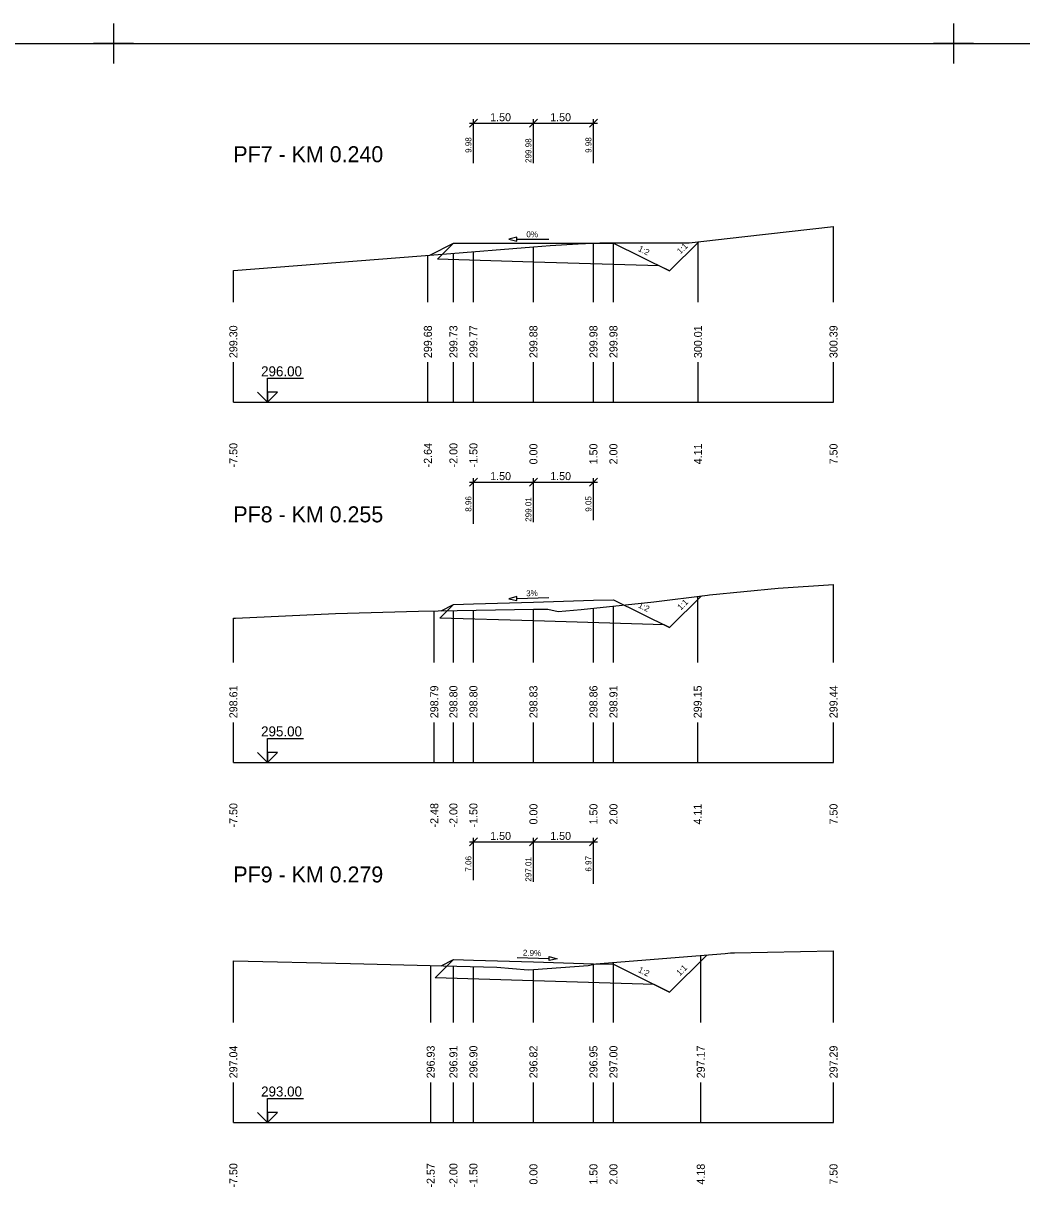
# Model space of a CAD drawing. Extents: x -5 to 1265, y -2 to 602.
# Drawn here: x 397.5 to 647, y 307.8 to 601.7 of the extents above; entities that cross this region are included whole.
import ezdxf

# ---------------------------------------------------------------- set-up
doc = ezdxf.new("R2010")
doc.units = 0
for name, color, linetype in [('KOTA', 7, 'Continuous'), ('KOTA_DELKY', 7, 'Continuous'), ('KOTA_DELKY_CONT', 7, 'Continuous'), ('NS_TELESO_VOZOVKY', 7, 'Continuous'), ('NS_V_PF', 7, 'Continuous'), ('REZY_PF_PUVODNI', 7, 'Continuous'), ('SESTAVY_REZU_PF', 7, 'Continuous'), ('SKLON', 7, 'Continuous'), ('SVK', 7, 'Continuous')]:
    doc.layers.add(name, color=color, linetype=linetype)

msp = doc.modelspace()

# ---------------------------------------------------------------- linework, layer by layer
for p, q in [((420, 601.67), (420, 591.67)), ((420, 601.67), (420, 591.67)), ((420, 601.67), (420, 591.67)), ((420, 601.67), (420, 591.67)), ((420, 601.67), (420, 591.67)), ((420, 601.67), (420, 591.67)), ((420, 601.67), (420, 591.67)), ((420, 601.67), (420, 591.67)), ((420, 601.67), (420, 591.67)), ((420, 601.67), (420, 591.67)), ((420, 601.67), (420, 591.67)), ((420, 601.67), (420, 591.67)), ((420, 601.67), (420, 591.67)), ((420, 601.67), (420, 591.67)), ((420, 601.67), (420, 591.67)), ((420, 601.67), (420, 591.67)), ((420, 601.67), (420, 591.67)), ((420, 601.67), (420, 591.67)), ((420, 601.67), (420, 591.67)), ((420, 601.67), (420, 591.67)), ((420, 601.67), (420, 591.67)), ((420, 601.67), (420, 591.67)), ((420, 601.67), (420, 591.67)), ((420, 601.67), (420, 591.67)), ((420, 601.67), (420, 591.67)), ((420, 601.67), (420, 591.67)), ((420, 601.67), (420, 591.67)), ((420, 601.67), (420, 591.67)), ((420, 601.67), (420, 591.67)), ((420, 601.67), (420, 591.67)), ((420, 601.67), (420, 591.67)), ((420, 601.67), (420, 591.67)), ((420, 601.67), (420, 591.67)), ((420, 601.67), (420, 591.67)), ((420, 601.67), (420, 591.67)), ((420, 601.67), (420, 591.67)), ((420, 601.67), (420, 591.67)), ((420, 601.67), (420, 591.67)), ((420, 601.67), (420, 591.67)), ((420, 601.67), (420, 591.67)), ((420, 601.67), (420, 591.67)), ((420, 601.67), (420, 591.67)), ((420, 601.67), (420, 591.67)), ((420, 601.67), (420, 591.67)), ((420, 601.67), (420, 591.67)), ((420, 601.67), (420, 591.67)), ((420, 601.67), (420, 591.67)), ((420, 601.67), (420, 591.67)), ((420, 601.67), (420, 591.67)), ((420, 601.67), (420, 591.67)), ((420, 601.67), (420, 591.67)), ((420, 601.67), (420, 591.67)), ((420, 601.67), (420, 591.67)), ((420, 601.67), (420, 591.67)), ((630, 601.67), (630, 591.67)), ((630, 601.67), (630, 591.67)), ((630, 601.67), (630, 591.67)), ((630, 601.67), (630, 591.67)), ((630, 601.67), (630, 591.67)), ((630, 601.67), (630, 591.67)), ((630, 601.67), (630, 591.67)), ((630, 601.67), (630, 591.67)), ((630, 601.67), (630, 591.67)), ((630, 601.67), (630, 591.67)), ((630, 601.67), (630, 591.67)), ((630, 601.67), (630, 591.67)), ((630, 601.67), (630, 591.67)), ((630, 601.67), (630, 591.67)), ((630, 601.67), (630, 591.67)), ((630, 601.67), (630, 591.67)), ((630, 601.67), (630, 591.67)), ((630, 601.67), (630, 591.67)), ((630, 601.67), (630, 591.67)), ((630, 601.67), (630, 591.67)), ((630, 601.67), (630, 591.67)), ((630, 601.67), (630, 591.67)), ((630, 601.67), (630, 591.67)), ((630, 601.67), (630, 591.67)), ((630, 601.67), (630, 591.67)), ((630, 601.67), (630, 591.67)), ((630, 601.67), (630, 591.67)), ((630, 601.67), (630, 591.67)), ((630, 601.67), (630, 591.67)), ((630, 601.67), (630, 591.67)), ((630, 601.67), (630, 591.67)), ((630, 601.67), (630, 591.67)), ((630, 601.67), (630, 591.67)), ((630, 601.67), (630, 591.67)), ((630, 601.67), (630, 591.67)), ((630, 601.67), (630, 591.67)), ((630, 601.67), (630, 591.67)), ((630, 601.67), (630, 591.67)), ((630, 601.67), (630, 591.67)), ((630, 601.67), (630, 591.67)), ((630, 601.67), (630, 591.67)), ((630, 601.67), (630, 591.67)), ((630, 601.67), (630, 591.67)), ((630, 601.67), (630, 591.67)), ((630, 601.67), (630, 591.67)), ((630, 601.67), (630, 591.67)), ((630, 601.67), (630, 591.67)), ((630, 601.67), (630, 591.67)), ((630, 601.67), (630, 591.67)), ((630, 601.67), (630, 591.67)), ((630, 601.67), (630, 591.67)), ((630, 601.67), (630, 591.67)), ((630, 601.67), (630, 591.67)), ((630, 601.67), (630, 591.67)), ((425, 596.67), (415, 596.67)), ((425, 596.67), (415, 596.67)), ((425, 596.67), (415, 596.67)), ((425, 596.67), (415, 596.67)), ((425, 596.67), (415, 596.67)), ((425, 596.67), (415, 596.67)), ((425, 596.67), (415, 596.67)), ((425, 596.67), (415, 596.67)), ((425, 596.67), (415, 596.67)), ((425, 596.67), (415, 596.67)), ((425, 596.67), (415, 596.67)), ((425, 596.67), (415, 596.67)), ((425, 596.67), (415, 596.67)), ((425, 596.67), (415, 596.67)), ((425, 596.67), (415, 596.67)), ((425, 596.67), (415, 596.67)), ((425, 596.67), (415, 596.67)), ((425, 596.67), (415, 596.67)), ((425, 596.67), (415, 596.67)), ((425, 596.67), (415, 596.67)), ((425, 596.67), (415, 596.67)), ((425, 596.67), (415, 596.67)), ((425, 596.67), (415, 596.67)), ((425, 596.67), (415, 596.67)), ((425, 596.67), (415, 596.67)), ((425, 596.67), (415, 596.67)), ((425, 596.67), (415, 596.67)), ((425, 596.67), (415, 596.67)), ((425, 596.67), (415, 596.67)), ((425, 596.67), (415, 596.67)), ((425, 596.67), (415, 596.67)), ((425, 596.67), (415, 596.67)), ((425, 596.67), (415, 596.67)), ((425, 596.67), (415, 596.67)), ((425, 596.67), (415, 596.67)), ((425, 596.67), (415, 596.67)), ((425, 596.67), (415, 596.67)), ((425, 596.67), (415, 596.67)), ((425, 596.67), (415, 596.67)), ((425, 596.67), (415, 596.67)), ((425, 596.67), (415, 596.67)), ((425, 596.67), (415, 596.67)), ((425, 596.67), (415, 596.67)), ((425, 596.67), (415, 596.67)), ((425, 596.67), (415, 596.67)), ((425, 596.67), (415, 596.67)), ((425, 596.67), (415, 596.67)), ((425, 596.67), (415, 596.67)), ((425, 596.67), (415, 596.67)), ((425, 596.67), (415, 596.67)), ((425, 596.67), (415, 596.67)), ((425, 596.67), (415, 596.67)), ((425, 596.67), (415, 596.67)), ((425, 596.67), (415, 596.67)), ((635, 596.67), (625, 596.67)), ((635, 596.67), (625, 596.67)), ((635, 596.67), (625, 596.67)), ((635, 596.67), (625, 596.67)), ((635, 596.67), (625, 596.67)), ((635, 596.67), (625, 596.67)), ((635, 596.67), (625, 596.67)), ((635, 596.67), (625, 596.67)), ((635, 596.67), (625, 596.67)), ((635, 596.67), (625, 596.67)), ((635, 596.67), (625, 596.67)), ((635, 596.67), (625, 596.67)), ((635, 596.67), (625, 596.67)), ((635, 596.67), (625, 596.67)), ((635, 596.67), (625, 596.67)), ((635, 596.67), (625, 596.67)), ((635, 596.67), (625, 596.67)), ((635, 596.67), (625, 596.67)), ((635, 596.67), (625, 596.67)), ((635, 596.67), (625, 596.67)), ((635, 596.67), (625, 596.67)), ((635, 596.67), (625, 596.67)), ((635, 596.67), (625, 596.67)), ((635, 596.67), (625, 596.67)), ((635, 596.67), (625, 596.67)), ((635, 596.67), (625, 596.67)), ((635, 596.67), (625, 596.67)), ((635, 596.67), (625, 596.67)), ((635, 596.67), (625, 596.67)), ((635, 596.67), (625, 596.67)), ((635, 596.67), (625, 596.67)), ((635, 596.67), (625, 596.67)), ((635, 596.67), (625, 596.67)), ((635, 596.67), (625, 596.67)), ((635, 596.67), (625, 596.67)), ((635, 596.67), (625, 596.67)), ((635, 596.67), (625, 596.67)), ((635, 596.67), (625, 596.67)), ((635, 596.67), (625, 596.67)), ((635, 596.67), (625, 596.67)), ((635, 596.67), (625, 596.67)), ((635, 596.67), (625, 596.67)), ((635, 596.67), (625, 596.67)), ((635, 596.67), (625, 596.67)), ((635, 596.67), (625, 596.67)), ((635, 596.67), (625, 596.67)), ((635, 596.67), (625, 596.67)), ((635, 596.67), (625, 596.67)), ((635, 596.67), (625, 596.67)), ((635, 596.67), (625, 596.67)), ((635, 596.67), (625, 596.67)), ((635, 596.67), (625, 596.67)), ((635, 596.67), (625, 596.67)), ((635, 596.67), (625, 596.67))]:
    msp.add_line(p, q)
msp.add_lwpolyline([(0, 596.67), (1260, 596.67), (1260, 2.67), (0, 2.67)], close=True)
at = {"layer": 'KOTA'}
for points in [[(458.51, 507), (456.01, 509.5), (458.51, 507), (458.51, 513), (467.51, 513)], [(458.51, 507), (461.01, 509.5), (458.51, 509.5), (458.51, 507)], [(458.51, 507), (461.01, 509.5), (458.51, 509.5)], [(458.51, 417), (456.01, 419.5), (458.51, 417), (458.51, 423), (467.51, 423)], [(458.51, 417), (461.01, 419.5), (458.51, 419.5), (458.51, 417)], [(458.51, 417), (461.01, 419.5), (458.51, 419.5)], [(458.51, 327), (456.01, 329.5), (458.51, 327), (458.51, 333), (467.51, 333)], [(458.51, 327), (461.01, 329.5), (458.51, 329.5), (458.51, 327)], [(458.51, 327), (461.01, 329.5), (458.51, 329.5)]]:
    msp.add_lwpolyline(points, dxfattribs=at)
at = {"layer": 'KOTA_DELKY'}
for points in [[(509, 575.75), (511, 577.75)], [(509, 576.75), (526, 576.75)], [(510, 566.75), (510, 577.75)], [(524, 575.75), (526, 577.75)], [(524, 575.75), (526, 577.75)], [(524, 576.75), (541, 576.75)], [(525, 566.75), (525, 577.75)], [(525, 566.75), (525, 577.75)], [(539, 575.75), (541, 577.75)], [(540, 566.75), (540, 577.75)], [(509, 486.06), (511, 488.06)], [(510, 476.61), (510, 488.06)], [(524, 486.06), (526, 488.06)], [(524, 486.06), (526, 488.06)], [(525, 477.06), (525, 488.06)], [(525, 477.06), (525, 488.06)], [(539, 486.06), (541, 488.06)], [(540, 477.51), (540, 488.06)], [(509, 487.06), (526, 487.06)], [(524, 487.06), (541, 487.06)], [(509, 396.12), (511, 398.12)], [(509, 397.12), (526, 397.12)], [(510, 387.57), (510, 398.12)], [(524, 396.12), (526, 398.12)], [(524, 396.12), (526, 398.12)], [(524, 397.12), (541, 397.12)], [(525, 387.12), (525, 398.12)], [(525, 387.12), (525, 398.12)], [(539, 396.12), (541, 398.12)], [(540, 386.68), (540, 398.12)]]:
    msp.add_lwpolyline(points, dxfattribs=at)
at = {"layer": 'NS_TELESO_VOZOVKY'}
for points in [[(525, 546.75), (540, 546.75), (545, 546.75), (559.01, 539.82), (556.41, 541.11), (525, 542.05), (501.02, 542.77), (505, 546.75), (510, 546.75), (525, 546.75)], [(525, 457.06), (540, 457.51), (545, 457.66), (559.01, 450.73), (557.7, 451.38), (525, 452.36), (501.6, 453.06), (505, 456.46), (510, 456.61), (525, 457.06)], [(525, 367.12), (540, 366.68), (545, 366.54), (559.01, 359.61), (555.14, 361.52), (525, 362.42), (500.45, 363.16), (505, 367.71), (510, 367.57), (525, 367.12)]]:
    msp.add_lwpolyline(points, dxfattribs=at)
at = {"layer": 'NS_V_PF'}
for points in [[(499.1, 543.8), (505, 546.75), (510, 546.75), (525, 546.75), (540, 546.75), (545, 546.75), (559.01, 539.82), (566.37, 547.11)], [(501.91, 454.92), (505, 456.46), (510, 456.61), (525, 457.06), (540, 457.51), (545, 457.66), (559.01, 450.73), (566.99, 458.63)], [(501.95, 366.19), (505, 367.71), (510, 367.57), (525, 367.12), (540, 366.68), (545, 366.54), (559.01, 359.61), (568.35, 368.85)]]:
    msp.add_lwpolyline(points, dxfattribs=at)
at = {"layer": 'REZY_PF_PUVODNI'}
for points in [[(450, 539.96), (502.25, 544.05), (525, 545.83), (525, 545.83), (529.2, 546.16), (536.16, 546.64), (541.58, 546.84), (563.94, 546.83), (577.8, 548.4), (600, 550.9)], [(450, 453.08), (450.55, 453.09), (475.56, 454.2), (496.3, 454.77), (501.21, 454.91), (525, 455.26), (528.59, 455.32), (531.17, 454.75), (536.95, 455.23), (555.13, 457.15), (568.5, 458.81), (569.03, 458.88), (586.15, 460.55), (600, 461.44)], [(450, 367.42), (479.27, 366.73), (515.86, 365.86), (523.66, 365.15), (525, 365.25), (525, 365.25), (538.66, 366.23), (540.56, 366.62), (572.92, 369.22), (574.24, 369.39), (574.4, 369.4), (575.24, 369.45), (600, 369.9)]]:
    msp.add_lwpolyline(points, dxfattribs=at)
at = {"layer": 'SESTAVY_REZU_PF'}
for points in [[(450, 507), (600, 507)], [(450, 417), (600, 417)], [(450, 327), (600, 327)]]:
    msp.add_lwpolyline(points, dxfattribs=at)
at = {"layer": 'SKLON'}
for points in [[(520.88, 548.25), (518.88, 547.75), (520.88, 547.25)], [(520.84, 458.44), (518.86, 457.88), (520.87, 457.44)], [(528.93, 368.51), (530.91, 367.95), (528.9, 367.51)]]:
    msp.add_lwpolyline(points, close=True, dxfattribs=at)
for points in [[(520.88, 548.25), (518.88, 547.75), (520.88, 547.25), (520.88, 548.25)], [(520.88, 547.75), (528.88, 547.75)], [(520.84, 458.44), (518.86, 457.88), (520.87, 457.44), (520.84, 458.44)], [(520.86, 457.94), (528.85, 458.18)], [(520.92, 368.25), (528.91, 368.01)], [(528.93, 368.51), (530.91, 367.95), (528.9, 367.51), (528.93, 368.51)]]:
    msp.add_lwpolyline(points, dxfattribs=at)
at = {"layer": 'SVK'}
for points in [[(600, 532), (600, 550.9)], [(540, 532), (540, 546.79)], [(545, 532), (545, 546.84)], [(566.14, 532), (566.14, 547.08)], [(498.61, 532), (498.61, 543.76)], [(505, 532), (505, 544.26)], [(510, 532), (510, 544.65)], [(525, 532), (525, 545.83)], [(450, 532), (450, 539.96)], [(450, 507), (450, 517)], [(498.61, 507), (498.61, 517)], [(505, 507), (505, 517)], [(510, 507), (510, 517)], [(525, 507), (525, 517)], [(540, 507), (540, 517)], [(545, 507), (545, 517)], [(566.14, 507), (566.14, 517)], [(600, 507), (600, 517)], [(600, 442), (600, 461.44)], [(566.05, 442), (566.05, 458.51)], [(540, 442), (540, 455.55)], [(545, 442), (545, 456.08)], [(450, 442), (450, 453.08)], [(500.22, 442), (500.22, 454.88)], [(505, 442), (505, 454.96)], [(510, 442), (510, 455.04)], [(525, 442), (525, 455.26)], [(450, 417), (450, 427)], [(500.22, 417), (500.22, 427)], [(505, 417), (505, 427)], [(510, 417), (510, 427)], [(525, 417), (525, 427)], [(540, 417), (540, 427)], [(545, 417), (545, 427)], [(566.05, 417), (566.05, 427)], [(600, 417), (600, 427)], [(450, 352), (450, 367.42)], [(566.83, 352), (566.83, 368.73)], [(600, 352), (600, 369.9)], [(499.32, 352), (499.32, 366.25)], [(505, 352), (505, 366.12)], [(510, 352), (510, 366)], [(525, 352), (525, 365.25)], [(540, 352), (540, 366.51)], [(545, 352), (545, 366.98)], [(450, 327), (450, 337)], [(499.32, 327), (499.32, 337)], [(505, 327), (505, 337)], [(510, 327), (510, 337)], [(525, 327), (525, 337)], [(540, 327), (540, 337)], [(545, 327), (545, 337)], [(566.83, 327), (566.83, 337)], [(600, 327), (600, 337)]]:
    msp.add_lwpolyline(points, dxfattribs=at)

# ---------------------------------------------------------------- texts
at = {"layer": 'KOTA'}
for s, p in [('296.00', (456.93, 513.5)), ('295.00', (456.93, 423.5)), ('293.00', (456.93, 333.5))]:
    msp.add_text(s, height=2.5, dxfattribs=at).set_placement(p)
at = {"layer": 'KOTA_DELKY'}
for p in [(514.19, 577.25), (529.19, 577.25), (514.19, 487.56), (529.19, 487.56), (514.19, 397.62), (529.19, 397.62)]:
    msp.add_text('1.50', height=2, dxfattribs=at).set_placement(p)
at = {"layer": 'KOTA_DELKY_CONT'}
for s, p in [('9.98', (509.5, 569.34)), ('9.98', (539.5, 569.34)), ('299.98', (524.5, 566.83)), ('8.96', (509.5, 479.65)), ('299.01', (524.5, 477.14)), ('9.05', (539.5, 479.65)), ('7.06', (509.5, 389.71)), ('297.01', (524.5, 387.2)), ('6.97', (539.5, 389.71))]:
    msp.add_text(s, height=1.5, rotation=90, dxfattribs=at).set_placement(p)
at = {"layer": 'SESTAVY_REZU_PF'}
for s, p in [('PF7 - KM 0.240', (450, 567)), ('PF8 - KM 0.255', (450, 477)), ('PF9 - KM 0.279', (450, 387))]:
    msp.add_text(s, height=4, dxfattribs=at).set_placement(p)
at = {"layer": 'SKLON'}
for s, rotation, p in [('0%', 0.0036, (523.24, 548.25)), ('1:2', 333.679, (551.04, 544.88)), ('1:1', 44.7149, (561.74, 543.93)), ('3%', 1.7184, (523.2, 458.51)), ('1:2', 333.679, (551.04, 455.79)), ('1:1', 44.7149, (561.83, 454.93)), ('2.9%', 358.3157, (522.34, 368.7)), ('1:2', 333.679, (551.04, 364.67)), ('1:1', 44.7149, (561.58, 363.56))]:
    msp.add_text(s, height=1.5, rotation=rotation, dxfattribs=at).set_placement(p)
at = {"layer": 'SVK'}
for s, p in [(' 299.30', (451, 517.3)), (' 299.68', (499.61, 517.3)), (' 299.73', (506, 517.3)), (' 299.77', (511, 517.3)), (' 299.88', (526, 517.3)), (' 299.98', (541, 517.3)), (' 299.98', (546, 517.3)), (' 300.01', (567.14, 517.3)), (' 300.39', (601, 517.3)), (' -7.50', (451, 490)), (' -2.64', (499.61, 490)), (' -2.00', (506, 490)), (' -1.50', (511, 490)), ('  0.00', (526, 490)), ('  1.50', (541, 490)), ('  2.00', (546, 490)), ('  4.11', (567.14, 490)), ('  7.50', (601, 490)), (' 298.61', (451, 427.3)), (' 298.79', (501.22, 427.3)), (' 298.80', (506, 427.3)), (' 298.80', (511, 427.3)), (' 298.83', (526, 427.3)), (' 298.86', (541, 427.3)), (' 298.91', (546, 427.3)), (' 299.15', (567.05, 427.3)), (' 299.44', (601, 427.3)), (' -7.50', (451, 400)), (' -2.48', (501.22, 400)), (' -2.00', (506, 400)), (' -1.50', (511, 400)), ('  0.00', (526, 400)), ('  1.50', (541, 400)), ('  2.00', (546, 400)), ('  4.11', (567.05, 400)), ('  7.50', (601, 400)), (' 297.04', (451, 337.3)), (' 296.93', (500.32, 337.3)), (' 296.91', (506, 337.3)), (' 296.90', (511, 337.3)), (' 296.82', (526, 337.3)), (' 296.95', (541, 337.3)), (' 297.00', (546, 337.3)), (' 297.17', (567.83, 337.3)), (' 297.29', (601, 337.3)), (' -7.50', (451, 310)), (' -2.57', (500.32, 310)), (' -2.00', (506, 310)), (' -1.50', (511, 310)), ('  0.00', (526, 310)), ('  1.50', (541, 310)), ('  2.00', (546, 310)), ('  4.18', (567.83, 310)), ('  7.50', (601, 310))]:
    msp.add_text(s, height=2, rotation=90, dxfattribs=at).set_placement(p)

doc.saveas('drawing.dxf')
